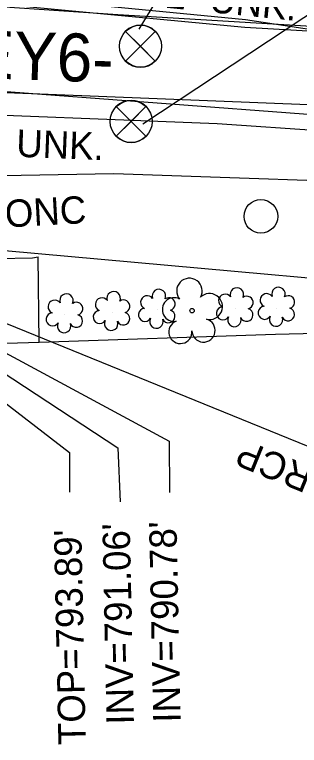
# Model space of a CAD drawing. Extents: x 1627482 to 1629573, y 760826 to 766301.
# Drawn here: x 1628499.5 to 1628541.1, y 763079.7 to 763186.4 of the extents above; entities that cross this region are included whole.
import ezdxf

# ---------------------------------------------------------------- set-up
doc = ezdxf.new("R2010")
doc.units = 0
for name, color, linetype in [('Exist Horizontal Alignment', 7, 'Continuous'), ('Exist Horizontal Alignment Direction Label', 7, 'Continuous'), ('Exist Other Culture Area Outline', 7, 'Continuous'), ('Exist Other Culture Area Outline Text', 7, 'Continuous'), ('Exist Right of Way Line', 7, 'Continuous'), ('Exist Roads EOP', 7, 'Continuous'), ('Exist Roads EOP Other', 7, 'Continuous'), ('Exist Structure Minor Catch Basin Leader', 7, 'Continuous'), ('Exist Structure Minor Catch Basin Top Elevation', 7, 'Continuous'), ('Exist Structure Minor Pipes RCP 15 Inch', 7, 'Continuous'), ('Exist Structure Minor Pipes RCP 15 Inch Invert', 7, 'Continuous'), ('Exist Structure Minor Pipes RCP 15 Inch Leader', 7, 'Continuous'), ('Exist Structure Minor Pipes RCP 15 Inch Text', 7, 'Continuous'), ('Exist Utilities Gas UG Line SUE LOS B', 7, 'Continuous'), ('Exist Utilities Other Pole CELL', 7, 'Continuous'), ('Exist Utilities Sanitary Sewer UG Line', 7, 'Continuous'), ('Exist Utilities Water Test Hole SUE LOS A CELL', 7, 'Continuous'), ('Exist Utilities Water Test Hole SUE LOS A Leader', 7, 'Continuous'), ('Exist Utilities Water UG Line SUE LOS B', 7, 'Continuous'), ('Exist Utilities Water UG Line SUE LOS B Text', 7, 'Continuous'), ('Exist Vegetation Shrub CELL', 7, 'Continuous'), ('Exist Vegetation Tree CELL', 7, 'Continuous')]:
    doc.layers.add(name, color=color, linetype=linetype)

msp = doc.modelspace()

# ---------------------------------------------------------------- linework, layer by layer
at = {"layer": 'Exist Horizontal Alignment'}
msp.add_line((1628413.76, 763178.36), (1628562.52, 763172.46), dxfattribs=at)
at = {"layer": 'Exist Other Culture Area Outline'}
for p, q in [((1628467.05, 763150.01), (1628502.14, 763150.9)), ((1628502.14, 763150.9), (1628502.98, 763151.03)), ((1628503.1, 763138.57), (1628502.98, 763151.03))]:
    msp.add_line(p, q, dxfattribs=at)
at = {"layer": 'Exist Right of Way Line'}
msp.add_lwpolyline([(1628444, 762943.51), (1628435.83, 763157.53), (1628641.44, 763139.04)], dxfattribs=at)
at = {"layer": 'Exist Roads EOP'}
for points in [[(1628563.09, 763183.45), (1628514.59, 763186.36), (1628477.19, 763188.93), (1628470.8, 763192.21), (1628459.22, 763192.87), (1628459.17, 763191.1)], [(1628561.94, 763161.47), (1628513.99, 763163.13), (1628481.48, 763162.58), (1628481.22, 763160.3), (1628469.48, 763160.36), (1628468.06, 763161.84), (1628467.96, 763163.9), (1628461.84, 763163.87)]]:
    msp.add_lwpolyline(points, dxfattribs=at)
at = {"layer": 'Exist Roads EOP Other'}
msp.add_line((1628498.37, 763138.42), (1628503.1, 763138.57), dxfattribs=at)
msp.add_lwpolyline([(1628503.1, 763138.57), (1628537.61, 763139.71), (1628565.87, 763140.43), (1628566.34, 763130.94), (1628566.85, 763128.4), (1628567.69, 763126.11), (1628568.68, 763125.1), (1628570.15, 763124.7), (1628571.71, 763124.77), (1628573.88, 763125.33), (1628576.17, 763126.78), (1628577.73, 763129.06), (1628578.42, 763131.22), (1628578.77, 763133.44), (1628577.96, 763137.15), (1628575.44, 763142.88), (1628573.36, 763146.66), (1628570.91, 763148.87), (1628568.85, 763150.32), (1628566.4, 763151.38), (1628560.69, 763153.16), (1628553.16, 763155.48), (1628550.57, 763156.58), (1628550.46, 763160.88)], dxfattribs=at)
at = {"layer": 'Exist Structure Minor Catch Basin Leader'}
msp.add_lwpolyline([(1628467.98, 763152.95), (1628507.52, 763122.43), (1628507.56, 763116.66)], dxfattribs=at)
at = {"layer": 'Exist Structure Minor Pipes RCP 15 Inch'}
msp.add_line((1628468.38, 763153.47), (1628558.13, 763116.92), dxfattribs=at)
at = {"layer": 'Exist Structure Minor Pipes RCP 15 Inch Leader'}
for points in [[(1628467.4, 763153.62), (1628522.09, 763124.1), (1628522.16, 763116.62)], [(1628468.38, 763153.47), (1628514.58, 763123.13), (1628514.96, 763115.25)]]:
    msp.add_lwpolyline(points, dxfattribs=at)
at = {"layer": 'Exist Utilities Gas UG Line SUE LOS B'}
msp.add_lwpolyline([(1628427.64, 763192.64), (1628478.03, 763189.83), (1628533.14, 763184.56), (1628565.03, 763182.73), (1628602.18, 763179.49)], dxfattribs=at)
at = {"layer": 'Exist Utilities Other Pole CELL'}
msp.add_circle((1628535.49, 763156.94), 2.46, dxfattribs=at)
at = {"layer": 'Exist Utilities Sanitary Sewer UG Line'}
msp.add_line((1628483.28, 763176.31), (1628740, 763156.94), dxfattribs=at)
at = {"layer": 'Exist Utilities Water Test Hole SUE LOS A CELL'}
for points in [[(1628520.07, 763183.96), (1628515.73, 763179.61), (1628517.9, 763181.79), (1628515.73, 763183.96), (1628520.07, 763179.61)], [(1628515.73, 763183.96), (1628517.9, 763181.79), (1628520.07, 763183.96)], [(1628520.07, 763179.61), (1628517.9, 763181.79), (1628515.73, 763179.61)], [(1628518.71, 763172.97), (1628514.36, 763168.63), (1628516.54, 763170.8), (1628514.36, 763172.97), (1628518.71, 763168.63)], [(1628514.36, 763172.97), (1628516.54, 763170.8), (1628518.71, 763172.97)], [(1628518.71, 763168.63), (1628516.54, 763170.8), (1628514.36, 763168.63)]]:
    msp.add_lwpolyline(points, dxfattribs=at)
for centre in [(1628517.9, 763181.79), (1628516.54, 763170.8)]:
    msp.add_circle(centre, 3.07, dxfattribs=at)
for centre, start, end in [((1628517.9, 763181.79), 45, 135), ((1628517.9, 763181.79), 225, 315), ((1628516.54, 763170.8), 45, 135), ((1628516.54, 763170.8), 225, 315)]:
    msp.add_arc(centre, 3.07, start, end, dxfattribs=at)
at = {"layer": 'Exist Utilities Water Test Hole SUE LOS A Leader'}
msp.add_line((1628517.7, 763184.26), (1628548.53, 763235.27), dxfattribs=at)
msp.add_lwpolyline([(1628518.26, 763170.45), (1628588.78, 763217.11), (1628586.83, 763266.63)], dxfattribs=at)
at = {"layer": 'Exist Utilities Water UG Line SUE LOS B'}
for points in [[(1628424.63, 763194.29), (1628474.32, 763191.43), (1628533.26, 763185.71), (1628565.12, 763180.86), (1628602.01, 763177.75)], [(1628426.42, 763172.58), (1628435.2, 763172.7), (1628454.94, 763172.62), (1628484.42, 763172.23), (1628529.1, 763170.52), (1628575.97, 763167.29)]]:
    msp.add_lwpolyline(points, dxfattribs=at)
at = {"layer": 'Exist Vegetation Shrub CELL'}
for p, q in [((1628531.75, 763143.48), (1628531.75, 763143.48)), ((1628537.83, 763143.55), (1628537.83, 763143.55)), ((1628506.87, 763142.6), (1628506.87, 763142.6)), ((1628513.76, 763142.93), (1628513.76, 763142.93)), ((1628520.36, 763143.26), (1628520.36, 763143.26))]:
    msp.add_line(p, q, dxfattribs=at)
for centre, radius, start, end in [((1628531.98, 763145.52), 0.99, 334.8391, 200.4717), ((1628538.06, 763145.59), 0.99, 334.8391, 200.4717), ((1628507.1, 763144.64), 0.99, 334.8391, 200.4717), ((1628513.99, 763144.97), 0.99, 334.8391, 200.4717), ((1628520.59, 763145.3), 0.99, 334.8391, 200.4717), ((1628530.27, 763144.61), 0.968, 35.8908, 245.4216), ((1628536.34, 763144.68), 0.968, 35.8908, 245.4216), ((1628505.39, 763143.72), 0.968, 35.8908, 245.4216), ((1628508.55, 763143.46), 0.929, 284.4567, 126.0861), ((1628512.28, 763144.06), 0.968, 35.8908, 245.4216), ((1628515.43, 763143.8), 0.929, 284.4567, 126.0861), ((1628518.88, 763144.38), 0.968, 35.8908, 245.4216), ((1628522.04, 763144.13), 0.929, 284.4567, 126.0861), ((1628533.42, 763144.35), 0.929, 284.4567, 126.0861), ((1628539.5, 763144.42), 0.929, 284.4567, 126.0861), ((1628518.56, 763142.55), 0.955, 95.1099, 327.9534), ((1628529.95, 763142.78), 0.955, 95.1099, 327.9534), ((1628533.39, 763142.55), 0.937, 204.9913, 73.4601), ((1628536.03, 763142.85), 0.955, 95.1099, 327.9534), ((1628539.46, 763142.62), 0.937, 204.9913, 73.4601), ((1628505.07, 763141.89), 0.955, 95.1099, 327.9534), ((1628508.51, 763141.67), 0.937, 204.9913, 73.4601), ((1628511.96, 763142.23), 0.955, 95.1099, 327.9534), ((1628515.4, 763142), 0.937, 204.9913, 73.4601), ((1628522, 763142.33), 0.937, 204.9913, 73.4601), ((1628531.62, 763141.8), 0.984, 151.2797, 21.387), ((1628537.7, 763141.87), 0.984, 151.2797, 21.387), ((1628506.75, 763140.91), 0.984, 151.2797, 21.387), ((1628513.63, 763141.25), 0.984, 151.2797, 21.387), ((1628520.23, 763141.57), 0.984, 151.2797, 21.387)]:
    msp.add_arc(centre, radius, start, end, dxfattribs=at)
at = {"layer": 'Exist Vegetation Tree CELL'}
msp.add_line((1628525.44, 763143.17), (1628525.44, 763143.17), dxfattribs=at)
msp.add_circle((1628525.44, 763143.17), 0.326, dxfattribs=at)
for centre, radius, start, end in [((1628525.05, 763146.04), 1.86, 330.1651, 219.7134), ((1628527.98, 763143.76), 1.9, 257.1011, 134.1999), ((1628522.83, 763143.32), 1.73, 62.6636, 279.3457), ((1628523.73, 763140.05), 1.69, 111.5671, 6.231), ((1628527.11, 763140.27), 1.7, 181.2822, 74.56)]:
    msp.add_arc(centre, radius, start, end, dxfattribs=at)

# ---------------------------------------------------------------- texts
at = {"layer": 'Exist Horizontal Alignment Direction Label'}
msp.add_text('-EY6-', height=7, rotation=358.0598, dxfattribs=at).set_placement((1628489.97, 763177.27))
at = {"layer": 'Exist Other Culture Area Outline Text'}
msp.add_text('48" CONC', height=4, rotation=3.1481, dxfattribs=at).set_placement((1628485.03, 763154.58))
at = {"layer": 'Exist Structure Minor Catch Basin Top Elevation'}
msp.add_text("TOP=793.89'", height=4, rotation=91.1941, dxfattribs=at).set_placement((1628509.92, 763079.76))
at = {"layer": 'Exist Structure Minor Pipes RCP 15 Inch Invert'}
for s, p in [("INV=791.06'", (1628516.95, 763082.74)), ("INV=790.78'", (1628523.77, 763083.03))]:
    msp.add_text(s, height=4, rotation=91.1941, dxfattribs=at).set_placement(p)
at = {"layer": 'Exist Structure Minor Pipes RCP 15 Inch Text'}
msp.add_text('15" RCP', height=4, rotation=157.8368, dxfattribs=at).set_placement((1628552.07, 763116.65))
at = {"layer": 'Exist Utilities Water UG Line SUE LOS B Text'}
for rotation, p in [(354.2146, (1628521.52, 763187.42)), (357.8054, (1628493.35, 763165.89))]:
    msp.add_text('2" UNK.', height=4, rotation=rotation, dxfattribs=at).set_placement(p)

doc.saveas('drawing.dxf')
